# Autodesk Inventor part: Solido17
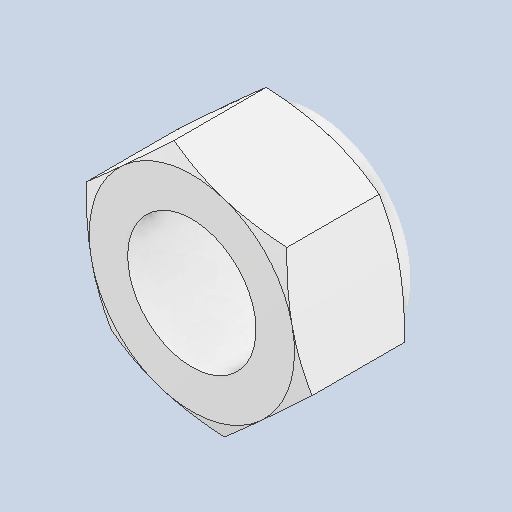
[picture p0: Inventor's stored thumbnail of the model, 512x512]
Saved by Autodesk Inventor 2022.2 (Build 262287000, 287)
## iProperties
Created: 2024-10
Part Number: Solido17
Material: Generico
Document SubType Name: Modeling
Designer: 18907419
Density: 1 g/cm^3
Appearance: Default
Author: 18907419
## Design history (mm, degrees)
feature "Solido17"
node "Solido1"
